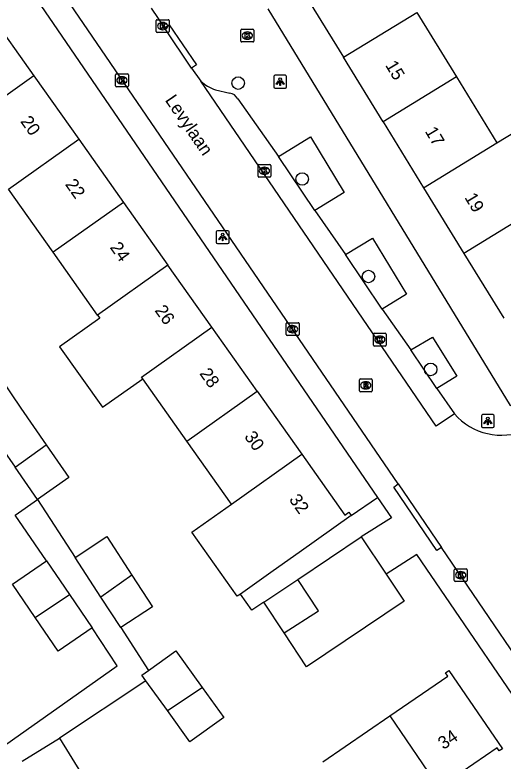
# Model space of a CAD drawing. Extents: x 157466 to 158888, y 383063 to 384677.
# Drawn here: x 158011.8 to 158049.9, y 383508.4 to 383566.6 of the extents above; entities that cross this region are included whole.
import ezdxf

# ---------------------------------------------------------------- set-up
doc = ezdxf.new("R2010")
doc.units = 0
for name, color, linetype in [('IMGEO_Boom', 7, 'Continuous'), ('IMGEO_Kolk', 7, 'Continuous'), ('IMGEO_Lichtpunt', 7, 'Continuous'), ('IMGEO_Openbare_ruimte_label', 7, 'Continuous'), ('IMGEO_Pand', 7, 'Continuous'), ('IMGEO_Pand_nummerreeks', 7, 'Continuous'), ('IMGEO_Parkeervlak_open', 7, 'Continuous'), ('IMGEO_Rijbaan_lokaal_open', 7, 'Continuous'), ('IMGEO_Rioolput', 7, 'Continuous'), ('IMGEO_Voetpad_open', 7, 'Continuous')]:
    doc.layers.add(name, color=color, linetype=linetype)

msp = doc.modelspace()

# ---------------------------------------------------------------- linework, layer by layer
at = {"layer": 'IMGEO_Boom'}
for centre in [(158029.219, 383561.321), (158034.217, 383553.831), (158039.396, 383546.219), (158044.258, 383538.967)]:
    msp.add_circle(centre, 0.489, dxfattribs=at)
at = {"layer": 'IMGEO_Kolk'}
for p, q in [((158022.893, 383566.27), (158023.745, 383566.27)), ((158022.818, 383565.344), (158022.818, 383566.196)), ((158023.306, 383566.05), (158023.331, 383566.05)), ((158023.819, 383566.196), (158023.819, 383565.344)), ((158023.745, 383565.27), (158022.893, 383565.27)), ((158023.329, 383565.49), (158023.304, 383565.49)), ((158029.435, 383564.605), (158029.435, 383565.457)), ((158029.51, 383565.531), (158030.362, 383565.531)), ((158029.923, 383565.311), (158029.948, 383565.311)), ((158030.436, 383565.457), (158030.436, 383564.605)), ((158030.362, 383564.531), (158029.51, 383564.531)), ((158029.946, 383564.751), (158029.921, 383564.751)), ((158019.636, 383561.114), (158019.636, 383561.966)), ((158019.711, 383562.04), (158020.563, 383562.04)), ((158020.124, 383561.82), (158020.149, 383561.82)), ((158020.637, 383561.966), (158020.637, 383561.114)), ((158020.563, 383561.04), (158019.711, 383561.04)), ((158020.147, 383561.26), (158020.122, 383561.26)), ((158030.767, 383554.046), (158030.767, 383554.898)), ((158030.842, 383554.972), (158031.694, 383554.972)), ((158031.255, 383554.752), (158031.28, 383554.752)), ((158031.768, 383554.898), (158031.768, 383554.046)), ((158031.278, 383554.192), (158031.253, 383554.192)), ((158031.694, 383553.972), (158030.842, 383553.972)), ((158032.971, 383541.688), (158032.971, 383542.54)), ((158033.046, 383542.614), (158033.898, 383542.614)), ((158033.459, 383542.394), (158033.484, 383542.394)), ((158033.972, 383542.54), (158033.972, 383541.688)), ((158033.482, 383541.834), (158033.457, 383541.834)), ((158039.863, 383541.79), (158040.715, 383541.79)), ((158033.898, 383541.614), (158033.046, 383541.614)), ((158039.788, 383540.864), (158039.788, 383541.716)), ((158040.276, 383541.57), (158040.301, 383541.57)), ((158040.789, 383541.716), (158040.789, 383540.864)), ((158040.715, 383540.79), (158039.863, 383540.79)), ((158040.299, 383541.01), (158040.274, 383541.01)), ((158046.107, 383522.481), (158046.107, 383523.333)), ((158046.182, 383523.407), (158047.034, 383523.407)), ((158046.595, 383523.187), (158046.62, 383523.187)), ((158047.108, 383523.333), (158047.108, 383522.481)), ((158046.618, 383522.627), (158046.593, 383522.627)), ((158047.034, 383522.407), (158046.182, 383522.407))]:
    msp.add_line(p, q, dxfattribs=at)
for points in [[(158022.893, 383566.27), (158023.745, 383566.27)], [(158022.818, 383565.344), (158022.818, 383566.196)], [(158023.139, 383565.97), (158023.262, 383565.97), (158023.262, 383565.819), (158023.392, 383565.97), (158023.556, 383565.97), (158023.41, 383565.819), (158023.563, 383565.57), (158023.411, 383565.57), (158023.326, 383565.734), (158023.262, 383565.667), (158023.262, 383565.57), (158023.139, 383565.57), (158023.139, 383565.97)], [(158023.819, 383566.196), (158023.819, 383565.344)], [(158023.745, 383565.27), (158022.893, 383565.27)], [(158029.435, 383564.605), (158029.435, 383565.457)], [(158029.51, 383565.531), (158030.362, 383565.531)], [(158029.756, 383565.231), (158029.879, 383565.231), (158029.879, 383565.08), (158030.009, 383565.231), (158030.173, 383565.231), (158030.027, 383565.08), (158030.18, 383564.831), (158030.028, 383564.831), (158029.943, 383564.995), (158029.879, 383564.928), (158029.879, 383564.831), (158029.756, 383564.831), (158029.756, 383565.231)], [(158030.436, 383565.457), (158030.436, 383564.605)], [(158030.362, 383564.531), (158029.51, 383564.531)], [(158019.636, 383561.114), (158019.636, 383561.966)], [(158019.711, 383562.04), (158020.563, 383562.04)], [(158019.957, 383561.74), (158020.08, 383561.74), (158020.08, 383561.589), (158020.21, 383561.74), (158020.374, 383561.74), (158020.228, 383561.589), (158020.381, 383561.34), (158020.229, 383561.34), (158020.144, 383561.504), (158020.08, 383561.437), (158020.08, 383561.34), (158019.957, 383561.34), (158019.957, 383561.74)], [(158020.637, 383561.966), (158020.637, 383561.114)], [(158020.563, 383561.04), (158019.711, 383561.04)], [(158030.767, 383554.046), (158030.767, 383554.898)], [(158030.842, 383554.972), (158031.694, 383554.972)], [(158031.088, 383554.672), (158031.211, 383554.672), (158031.211, 383554.521), (158031.341, 383554.672), (158031.505, 383554.672), (158031.359, 383554.521), (158031.512, 383554.272), (158031.36, 383554.272), (158031.275, 383554.436), (158031.211, 383554.369), (158031.211, 383554.272), (158031.088, 383554.272), (158031.088, 383554.672)], [(158031.768, 383554.898), (158031.768, 383554.046)], [(158031.694, 383553.972), (158030.842, 383553.972)], [(158032.971, 383541.688), (158032.971, 383542.54)], [(158033.046, 383542.614), (158033.898, 383542.614)], [(158033.972, 383542.54), (158033.972, 383541.688)], [(158033.292, 383542.314), (158033.415, 383542.314), (158033.415, 383542.163), (158033.545, 383542.314), (158033.709, 383542.314), (158033.563, 383542.163), (158033.716, 383541.914), (158033.564, 383541.914), (158033.479, 383542.078), (158033.415, 383542.011), (158033.415, 383541.914), (158033.292, 383541.914), (158033.292, 383542.314)], [(158039.863, 383541.79), (158040.715, 383541.79)], [(158033.898, 383541.614), (158033.046, 383541.614)], [(158039.788, 383540.864), (158039.788, 383541.716)], [(158040.109, 383541.49), (158040.232, 383541.49), (158040.232, 383541.339), (158040.362, 383541.49), (158040.526, 383541.49), (158040.38, 383541.339), (158040.533, 383541.09), (158040.381, 383541.09), (158040.296, 383541.254), (158040.232, 383541.187), (158040.232, 383541.09), (158040.109, 383541.09), (158040.109, 383541.49)], [(158040.789, 383541.716), (158040.789, 383540.864)], [(158040.715, 383540.79), (158039.863, 383540.79)], [(158046.107, 383522.481), (158046.107, 383523.333)], [(158046.182, 383523.407), (158047.034, 383523.407)], [(158046.428, 383523.107), (158046.551, 383523.107), (158046.551, 383522.956), (158046.681, 383523.107), (158046.845, 383523.107), (158046.699, 383522.956), (158046.852, 383522.707), (158046.7, 383522.707), (158046.615, 383522.871), (158046.551, 383522.804), (158046.551, 383522.707), (158046.428, 383522.707), (158046.428, 383523.107)], [(158047.108, 383523.333), (158047.108, 383522.481)], [(158047.034, 383522.407), (158046.182, 383522.407)]]:
    msp.add_lwpolyline(points, dxfattribs=at)
for centre, start, end in [((158022.895, 383566.194), 91.55205, 178.44795), ((158022.895, 383566.194), 91.55205, 178.44795), ((158023.743, 383566.194), 1.55205, 88.44795), ((158023.743, 383566.194), 1.55205, 88.44795), ((158022.895, 383565.346), 181.55205, 268.44795), ((158022.895, 383565.346), 181.55205, 268.44795), ((158023.743, 383565.346), 271.55205, 358.44795), ((158023.743, 383565.346), 271.55205, 358.44795), ((158029.512, 383565.455), 91.55205, 178.44795), ((158029.512, 383565.455), 91.55205, 178.44795), ((158030.36, 383565.455), 1.55205, 88.44795), ((158030.36, 383565.455), 1.55205, 88.44795), ((158029.512, 383564.607), 181.55205, 268.44795), ((158029.512, 383564.607), 181.55205, 268.44795), ((158030.36, 383564.607), 271.55205, 358.44795), ((158030.36, 383564.607), 271.55205, 358.44795), ((158019.713, 383561.964), 91.55205, 178.44795), ((158019.713, 383561.964), 91.55205, 178.44795), ((158020.561, 383561.964), 1.55205, 88.44795), ((158020.561, 383561.964), 1.55205, 88.44795), ((158019.713, 383561.116), 181.55205, 268.44795), ((158019.713, 383561.116), 181.55205, 268.44795), ((158020.561, 383561.116), 271.55205, 358.44795), ((158020.561, 383561.116), 271.55205, 358.44795), ((158030.844, 383554.896), 91.55205, 178.44795), ((158030.844, 383554.896), 91.55205, 178.44795), ((158031.692, 383554.896), 1.55205, 88.44795), ((158031.692, 383554.896), 1.55205, 88.44795), ((158030.844, 383554.048), 181.55205, 268.44795), ((158030.844, 383554.048), 181.55205, 268.44795), ((158031.692, 383554.048), 271.55205, 358.44795), ((158031.692, 383554.048), 271.55205, 358.44795), ((158033.048, 383542.538), 91.55205, 178.44795), ((158033.048, 383542.538), 91.55205, 178.44795), ((158033.896, 383542.538), 1.55205, 88.44795), ((158033.896, 383542.538), 1.55205, 88.44795), ((158039.865, 383541.714), 91.55205, 178.44795), ((158039.865, 383541.714), 91.55205, 178.44795), ((158040.713, 383541.714), 1.55205, 88.44795), ((158040.713, 383541.714), 1.55205, 88.44795), ((158033.048, 383541.69), 181.55205, 268.44795), ((158033.048, 383541.69), 181.55205, 268.44795), ((158033.896, 383541.69), 271.55205, 358.44795), ((158033.896, 383541.69), 271.55205, 358.44795), ((158039.865, 383540.866), 181.55205, 268.44795), ((158039.865, 383540.866), 181.55205, 268.44795), ((158040.713, 383540.866), 271.55205, 358.44795), ((158040.713, 383540.866), 271.55205, 358.44795), ((158046.184, 383523.331), 91.55205, 178.44795), ((158046.184, 383523.331), 91.55205, 178.44795), ((158047.032, 383523.331), 1.55205, 88.44795), ((158047.032, 383523.331), 1.55205, 88.44795), ((158046.184, 383522.483), 181.55205, 268.44795), ((158046.184, 383522.483), 181.55205, 268.44795), ((158047.032, 383522.483), 271.55205, 358.44795), ((158047.032, 383522.483), 271.55205, 358.44795)]:
    msp.add_arc(centre, 0.0765, start, end, dxfattribs=at)
for centre, major_axis, ratio, start_param, end_param in [((158023.305, 383565.77), (-0.387, 0.002), 0.722429, 4.712389, 7.853982), ((158023.33, 383565.77), (-0.39, 0.002), 0.717154, 1.570796, 4.712389), ((158029.922, 383565.031), (-0.387, 0.002), 0.722429, 4.712389, 7.853982), ((158029.947, 383565.031), (-0.39, 0.002), 0.717154, 1.570796, 4.712389), ((158020.123, 383561.54), (-0.387, 0.002), 0.722429, 4.712389, 7.853982), ((158020.148, 383561.54), (-0.39, 0.002), 0.717154, 1.570796, 4.712389), ((158031.254, 383554.472), (-0.387, 0.002), 0.722429, 4.712389, 7.853982), ((158031.279, 383554.472), (-0.39, 0.002), 0.717154, 1.570796, 4.712389), ((158033.458, 383542.114), (-0.387, 0.002), 0.722429, 4.712389, 7.853982), ((158033.483, 383542.114), (-0.39, 0.002), 0.717154, 1.570796, 4.712389), ((158040.275, 383541.29), (-0.387, 0.002), 0.722429, 4.712389, 7.853982), ((158040.3, 383541.29), (-0.39, 0.002), 0.717154, 1.570796, 4.712389), ((158046.594, 383522.907), (-0.387, 0.002), 0.722429, 4.712389, 7.853982), ((158046.619, 383522.907), (-0.39, 0.002), 0.717154, 1.570796, 4.712389)]:
    msp.add_ellipse(centre, major_axis=major_axis, ratio=ratio, start_param=start_param, end_param=end_param, dxfattribs=at)
at = {"layer": 'IMGEO_Lichtpunt'}
for p, q in [((158032.004, 383561.834), (158032.004, 383561.027)), ((158032.004, 383561.834), (158032.004, 383561.027)), ((158032.906, 383561.929), (158032.098, 383561.929)), ((158032.906, 383561.929), (158032.098, 383561.929)), ((158033, 383561.027), (158033, 383561.834)), ((158033, 383561.027), (158033, 383561.834)), ((158032.098, 383560.933), (158032.906, 383560.933)), ((158032.098, 383560.933), (158032.906, 383560.933)), ((158027.508, 383549.7), (158027.508, 383548.893)), ((158027.508, 383549.7), (158027.508, 383548.893)), ((158028.41, 383549.795), (158027.602, 383549.795)), ((158028.41, 383549.795), (158027.602, 383549.795)), ((158028.504, 383548.893), (158028.504, 383549.7)), ((158028.504, 383548.893), (158028.504, 383549.7)), ((158027.602, 383548.799), (158028.41, 383548.799)), ((158027.602, 383548.799), (158028.41, 383548.799)), ((158048.224, 383535.342), (158048.224, 383534.535)), ((158048.224, 383535.342), (158048.224, 383534.535)), ((158049.126, 383535.437), (158048.318, 383535.437)), ((158049.126, 383535.437), (158048.318, 383535.437)), ((158049.22, 383534.535), (158049.22, 383535.342)), ((158049.22, 383534.535), (158049.22, 383535.342)), ((158048.318, 383534.441), (158049.126, 383534.441)), ((158048.318, 383534.441), (158049.126, 383534.441))]:
    msp.add_line(p, q, dxfattribs=at)
for points in [[(158032.378, 383561.498), (158032.417, 383561.47), (158032.229, 383561.208), (158032.191, 383561.235), (158032.378, 383561.498)], [(158032.48, 383561.45), (158032.527, 383561.45), (158032.527, 383561.128), (158032.48, 383561.128), (158032.48, 383561.45)], [(158032.59, 383561.47), (158032.628, 383561.497), (158032.815, 383561.235), (158032.776, 383561.207), (158032.59, 383561.47)], [(158027.882, 383549.364), (158027.921, 383549.336), (158027.733, 383549.074), (158027.695, 383549.101), (158027.882, 383549.364)], [(158028.094, 383549.336), (158028.132, 383549.363), (158028.319, 383549.101), (158028.28, 383549.073), (158028.094, 383549.336)], [(158027.984, 383549.316), (158028.031, 383549.316), (158028.031, 383548.994), (158027.984, 383548.994), (158027.984, 383549.316)], [(158048.598, 383535.006), (158048.637, 383534.978), (158048.449, 383534.716), (158048.411, 383534.743), (158048.598, 383535.006)], [(158048.7, 383534.958), (158048.747, 383534.958), (158048.747, 383534.636), (158048.7, 383534.636), (158048.7, 383534.958)], [(158048.81, 383534.978), (158048.848, 383535.005), (158049.035, 383534.743), (158048.996, 383534.715), (158048.81, 383534.978)]]:
    msp.add_lwpolyline(points, dxfattribs=at)
for centre in [(158032.503, 383561.632), (158028.007, 383549.498), (158048.723, 383535.14)]:
    msp.add_circle(centre, 0.0994, dxfattribs=at)
for centre, start, end in [((158032.098, 383561.834), 90, 180), ((158032.098, 383561.834), 90, 180), ((158032.906, 383561.834), 0, 90), ((158032.906, 383561.834), 0, 90), ((158032.098, 383561.027), 180, 270), ((158032.098, 383561.027), 180, 270), ((158032.906, 383561.027), 270, 0), ((158032.906, 383561.027), 270, 360), ((158027.602, 383549.7), 90, 180), ((158027.602, 383549.7), 90, 180), ((158028.41, 383549.7), 0, 90), ((158028.41, 383549.7), 0, 90), ((158027.602, 383548.893), 180, 270), ((158027.602, 383548.893), 180, 270), ((158028.41, 383548.893), 270, 0), ((158028.41, 383548.893), 270, 360), ((158048.318, 383535.342), 90, 180), ((158048.318, 383535.342), 90, 180), ((158049.126, 383535.342), 0, 90), ((158049.126, 383535.342), 0, 90), ((158048.318, 383534.535), 180, 270), ((158048.318, 383534.535), 180, 270), ((158049.126, 383534.535), 270, 0), ((158049.126, 383534.535), 270, 360)]:
    msp.add_arc(centre, 0.0946, start, end, dxfattribs=at)
at = {"layer": 'IMGEO_Pand'}
for points in [[(158032.821, 383570.915), (158034.114, 383568.81), (158033.804, 383568.619), (158033.963, 383568.361), (158034.253, 383568.54), (158037.449, 383563.338)], [(158037.449, 383563.338), (158043.169, 383566.843)], [(158043.169, 383566.843), (158046.267, 383561.8)], [(158009.774, 383566.791), (158013.25, 383561.886)], [(158040.548, 383558.294), (158037.449, 383563.338)], [(158013.25, 383561.886), (158007.768, 383557.989)], [(158013.25, 383561.886), (158016.758, 383556.936)], [(158046.267, 383561.8), (158040.548, 383558.294)], [(158046.267, 383561.8), (158049.427, 383556.658)], [(158040.548, 383558.294), (158043.707, 383553.151)], [(158049.427, 383556.658), (158050.885, 383557.552), (158051.977, 383558.34), (158055.124, 383553.216), (158052.574, 383551.535)], [(158011.275, 383553.039), (158016.758, 383556.936)], [(158016.758, 383556.936), (158020.247, 383552.012)], [(158043.707, 383553.151), (158049.427, 383556.658)], [(158014.764, 383548.114), (158011.275, 383553.039)], [(158043.707, 383553.151), (158046.854, 383548.03)], [(158020.247, 383552.012), (158014.764, 383548.114)], [(158020.247, 383552.012), (158023.721, 383547.11)], [(158052.574, 383551.535), (158046.854, 383548.03)], [(158018.236, 383543.212), (158014.764, 383548.114)], [(158046.854, 383548.03), (158049.967, 383542.963)], [(158023.721, 383547.11), (158018.236, 383543.212)], [(158027.152, 383542.27), (158023.721, 383547.11)], [(158018.236, 383543.212), (158018.41, 383542.966), (158015.262, 383540.735), (158018.609, 383536.01), (158021.758, 383538.241)], [(158021.758, 383538.241), (158021.666, 383538.371), (158027.152, 383542.27)], [(158030.703, 383537.258), (158027.152, 383542.27)], [(158008.161, 383536.443), (158008.183, 383536.458), (158010.734, 383538.188), (158012.229, 383535.933), (158014.218, 383533.078)], [(158025.217, 383533.359), (158021.758, 383538.241)], [(158025.217, 383533.359), (158030.703, 383537.258)], [(158030.703, 383537.258), (158034.183, 383532.348)], [(158007.558, 383532.68), (158009.779, 383534.227), (158010.782, 383532.788), (158011.784, 383531.348)], [(158011.784, 383531.348), (158014.218, 383533.078)], [(158014.218, 383533.078), (158015.992, 383530.529), (158013.542, 383528.823)], [(158028.696, 383528.448), (158025.217, 383533.359)], [(158028.696, 383528.448), (158034.183, 383532.348)], [(158034.183, 383532.348), (158037.549, 383527.598), (158037.87, 383527.826), (158038.053, 383527.567)], [(158013.542, 383528.823), (158011.784, 383531.348)], [(158029.39, 383521.428), (158029.144, 383521.255), (158025.602, 383526.256), (158028.696, 383528.448)], [(158038.053, 383527.567), (158033.974, 383524.677), (158031.948, 383523.241), (158029.39, 383521.428)], [(158016.469, 383524.288), (158018.955, 383525.911), (158020.911, 383522.915)], [(158033.867, 383522.578), (158038.836, 383525.909)], [(158038.836, 383525.909), (158040.79, 383522.974)], [(158018.49, 383521.194), (158016.469, 383524.288)], [(158013.353, 383519.593), (158011.575, 383522.191), (158014.242, 383524.015)], [(158014.242, 383524.015), (158016.039, 383521.39)], [(158020.911, 383522.915), (158018.49, 383521.194)], [(158020.911, 383522.915), (158022.525, 383520.443), (158020.039, 383518.82)], [(158031.211, 383520.798), (158033.867, 383522.578)], [(158040.79, 383522.974), (158042.19, 383520.871), (158034.565, 383515.761), (158032.809, 383518.397)], [(158032.809, 383518.397), (158035.49, 383520.125), (158033.867, 383522.578)], [(158013.353, 383519.593), (158016.039, 383521.39)], [(158016.039, 383521.39), (158017.816, 383518.792)], [(158020.039, 383518.82), (158018.49, 383521.194)], [(158032.809, 383518.397), (158031.211, 383520.798)], [(158017.816, 383518.792), (158015.15, 383516.967), (158013.353, 383519.593)], [(158022.224, 383515.472), (158024.345, 383516.997), (158026.407, 383514.129)], [(158022.011, 383514.66), (158021.699, 383515.093), (158022.224, 383515.472)], [(158041.058, 383511.911), (158045.602, 383515.017), (158045.418, 383515.286), (158045.665, 383515.456), (158049.867, 383509.349), (158049.619, 383509.179), (158049.449, 383509.426), (158044.895, 383506.312)], [(158023.686, 383512.332), (158022.011, 383514.66)], [(158026.407, 383514.129), (158028.086, 383511.796), (158025.44, 383509.892), (158023.686, 383512.332)], [(158023.686, 383512.332), (158026.407, 383514.129)], [(158035.836, 383508.343), (158041.058, 383511.911)], [(158041.058, 383511.911), (158044.895, 383506.312)], [(158012.33, 383508.373), (158015.265, 383510.171)], [(158015.265, 383510.171), (158016.964, 383507.396)]]:
    msp.add_lwpolyline(points, dxfattribs=at)
at = {"layer": 'IMGEO_Parkeervlak_open'}
for points in [[(158035.2, 383551.377), (158032.357, 383555.595)], [(158040.458, 383543.684), (158037.598, 383547.934)], [(158044.734, 383537.473), (158042.709, 383540.498)]]:
    msp.add_lwpolyline(points, dxfattribs=at)
at = {"layer": 'IMGEO_Rijbaan_lokaal_open'}
for points in [[(158041.721, 383530.034), (158008.336, 383578.833)], [(158022.425, 383567.177), (158023.472, 383565.627)], [(158025.578, 383562.5), (158023.472, 383565.627)], [(158025.578, 383562.5), (158026.298, 383561.481)], [(158046.111, 383535.496), (158044.68, 383534.545), (158026.298, 383561.481)], [(158041.721, 383530.034), (158045.102, 383525.057)], [(158054.624, 383511.124), (158045.102, 383525.057)]]:
    msp.add_lwpolyline(points, dxfattribs=at)
msp.add_arc((158049.797, 383538.75), 4.916, 221.43861, 292.81473, dxfattribs=at)
at = {"layer": 'IMGEO_Rioolput'}
for p, q in [((158038.688, 383537.304), (158038.688, 383538.156)), ((158038.763, 383538.23), (158039.615, 383538.23)), ((158039.176, 383538.01), (158039.201, 383538.01)), ((158039.689, 383538.156), (158039.689, 383537.304)), ((158039.615, 383537.23), (158038.763, 383537.23)), ((158039.199, 383537.45), (158039.174, 383537.45))]:
    msp.add_line(p, q, dxfattribs=at)
for points in [[(158038.688, 383537.304), (158038.688, 383538.156)], [(158038.763, 383538.23), (158039.615, 383538.23)], [(158039.277, 383537.928), (158039.025, 383537.93), (158039.025, 383537.53)], [(158039.025, 383537.53), (158039.149, 383537.53), (158039.149, 383537.692), (158039.16, 383537.692)], [(158039.203, 383537.849), (158039.149, 383537.849), (158039.149, 383537.768)], [(158039.149, 383537.768), (158039.201, 383537.768)], [(158039.689, 383538.156), (158039.689, 383537.304)], [(158039.615, 383537.23), (158038.763, 383537.23)], [(158039.207, 383537.663), (158039.278, 383537.53), (158039.418, 383537.53), (158039.353, 383537.656)]]:
    msp.add_lwpolyline(points, dxfattribs=at)
for centre, radius, start, end in [((158038.765, 383538.154), 0.0765, 91.55205, 178.44795), ((158038.765, 383538.154), 0.0765, 91.55205, 178.44795), ((158039.159, 383537.639), 0.0533, 26.02933, 88.69889), ((158039.185, 383537.957), 0.19, 274.7715, 282.96867), ((158039.209, 383537.753), 0.0964, 77.00612, 93.18647), ((158039.223, 383537.81), 0.0378, 276.66336, 79.67722), ((158039.276, 383537.818), 0.109, 350.36119, 89.41601), ((158039.274, 383537.818), 0.112, 277.58423, 350.98172), ((158039.258, 383537.603), 0.108, 29.51342, 73.79051), ((158039.613, 383538.154), 0.0765, 1.55205, 88.44795), ((158039.613, 383538.154), 0.0765, 1.55205, 88.44795), ((158038.765, 383537.306), 0.0765, 181.55205, 268.44795), ((158038.765, 383537.306), 0.0765, 181.55205, 268.44795), ((158039.613, 383537.306), 0.0765, 271.55205, 358.44795), ((158039.613, 383537.306), 0.0765, 271.55205, 358.44795)]:
    msp.add_arc(centre, radius, start, end, dxfattribs=at)
for centre, major_axis, ratio, start_param, end_param in [((158039.175, 383537.73), (-0.387, 0.002), 0.722429, 4.712389, 7.853982), ((158039.2, 383537.73), (-0.39, 0.002), 0.717154, 1.570796, 4.712389)]:
    msp.add_ellipse(centre, major_axis=major_axis, ratio=ratio, start_param=start_param, end_param=end_param, dxfattribs=at)
at = {"layer": 'IMGEO_Voetpad_open'}
for points in [[(158005.973, 383578.779), (158040.104, 383528.972)], [(158050.532, 383536.094), (158050.495, 383536.153), (158031.566, 383567.132)], [(158023.472, 383565.627), (158023.834, 383565.859), (158025.965, 383562.747), (158025.578, 383562.5)], [(158027.448, 383560.806), (158028.562, 383560.548)], [(158029.179, 383560.084), (158032.357, 383555.595)], [(158032.357, 383555.595), (158034.858, 383557.135), (158037.504, 383552.791), (158035.2, 383551.377)], [(158035.2, 383551.377), (158037.598, 383547.934)], [(158037.598, 383547.934), (158039.718, 383549.205), (158042.378, 383544.853), (158040.458, 383543.684)], [(158040.458, 383543.684), (158042.709, 383540.498)], [(158042.709, 383540.498), (158044.401, 383541.483), (158046.313, 383538.446), (158044.734, 383537.473)], [(158044.734, 383537.473), (158046.111, 383535.496)], [(158045.102, 383525.057), (158044.749, 383524.82), (158041.384, 383529.778), (158041.721, 383530.034)], [(158038.053, 383527.567), (158040.104, 383528.972)], [(158040.104, 383528.972), (158041.185, 383527.394), (158038.836, 383525.909)], [(158014.242, 383524.015), (158011.787, 383527.601), (158013.542, 383528.823)], [(158013.542, 383528.823), (158016.469, 383524.288)], [(158053.556, 383507.29), (158053.975, 383508.693), (158053.979, 383508.706), (158043.18, 383524.51), (158040.79, 383522.974)], [(158031.211, 383520.798), (158030.279, 383520.173), (158029.39, 383521.428)], [(158010.049, 383508.984), (158019.772, 383515.834), (158017.816, 383518.792)], [(158020.039, 383518.82), (158022.224, 383515.472)], [(158022.011, 383514.66), (158015.265, 383510.171)]]:
    msp.add_lwpolyline(points, dxfattribs=at)
for centre, radius, start, end in [((158028.222, 383563.442), 2.748, 225.54528, 253.63255), ((158028.433, 383559.735), 0.823, 25.09529, 81.01648)]:
    msp.add_arc(centre, radius, start, end, dxfattribs=at)

# ---------------------------------------------------------------- texts
at = {"layer": 'IMGEO_Openbare_ruimte_label'}
msp.add_text('Levylaan', height=1, rotation=304.40523, dxfattribs=at).set_placement((158023.467, 383559.985))
at = {"layer": 'IMGEO_Pand_nummerreeks'}
for s, rotation, p in [('15', 300.95532, (158040.681, 383562.722)), ('20', 305.40285, (158012.163, 383558.332)), ('17', 300.95532, (158043.778, 383557.56)), ('22', 305.40422, (158015.658, 383553.414)), ('19', 300.95532, (158046.874, 383552.397)), ('24', 305.40422, (158019.158, 383548.489)), ('26', 305.40285, (158022.657, 383543.567)), ('28', 305.40285, (158026.157, 383538.643)), ('30', 305.40422, (158029.656, 383533.721)), ('32', 305.40285, (158033.15, 383528.804)), ('34', 34.36694, (158045.259, 383509.251))]:
    msp.add_text(s, height=1, rotation=rotation, dxfattribs=at).set_placement(p)

doc.saveas('drawing.dxf')
